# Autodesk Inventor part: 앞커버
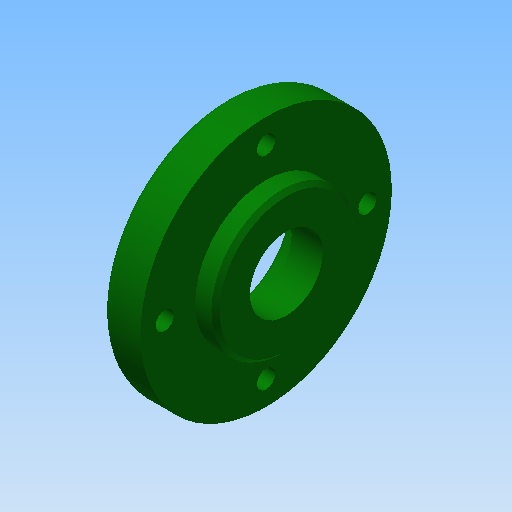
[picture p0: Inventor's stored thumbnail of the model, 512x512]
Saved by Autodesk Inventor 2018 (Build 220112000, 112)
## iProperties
Created: 2015-12
Part Number: 앞커버
Document SubType Name: Modeling
Designer: mdu
Density: 2.71 g/cm^3
Material: 알루미늄 6061
Mass: 70.9292 g
Surface Area: 93.9294 cm^2
Volume: 26.1731 cm^3
Appearance: 진녹색
Author: mdu
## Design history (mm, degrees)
sketch "스케치1"
  geometry: L1 (-7.5, 0)-(7.5, 0); L2 (-7.5, 0)-(-7.5, 31); L3 (-7.5, 31)-(2.5, 31); L4 (2.5, 31)-(2.5, 17.5); L5 (2.5, 17.5)-(7.5, 17.5); L6 (7.5, 17.5)-(7.5, 0); 2 further points
  constraints: 12 end point, 3 perpendicular, 1 coincident, 1 horizontal, 1 midpoint, 1 parallel
  dimensions: "d0" = 15 distance of L1.start L1.end; "d1" = 62 diameter of L3 L1; "d2" = 35 diameter of L5 L1; "d5" = 10 distance of L2.end L3.end
revolve "회전1" sketch "스케치1" stored, may be unused: angle "d6" = 90 deg
sketch "스케치2" dims "d42" = 50
  geometry: 3 further points
  constraints: 2 vertical alignment, 1 coincident, 2 other
hole "구멍1" sketch "스케치2" at (0, 25) diameter "d8" = 4.5; stored, may be unused: countersink angle "d12" = 90 deg, drill point angle "d14" = 118 deg; dims "d9" = 6, "d10" = 8, "d11" = 4.4, "d13" = 8
hole "구멍2" diameter "d20" = 18; stored, may be unused: countersink angle "d24" = 90 deg, drill point angle "d26" = 0 deg; dims "d18" = 10, "d19" = 10, "d21" = 6, "d22" = 8, "d23" = 4.4, "d25" = 8
hole "구멍3" diameter "d34" = 30; stored, may be unused: countersink angle "d38" = 90 deg, drill point angle "d40" = 0 deg; dims "d32" = 10, "d33" = 10, "d35" = 6, "d36" = 4, "d37" = 2, "d39" = 7.3
fillet "모깎기1" dims "d27" = 3, "d41" = 0.3
chamfer "모따기1" distance "d29" = 1; stored, may be unused: second distance "d30" = 2, angle "d31" = 45 deg
node "솔리드1"
pattern_circular "원형 패턴1" dims angle "d16" = 360 deg
